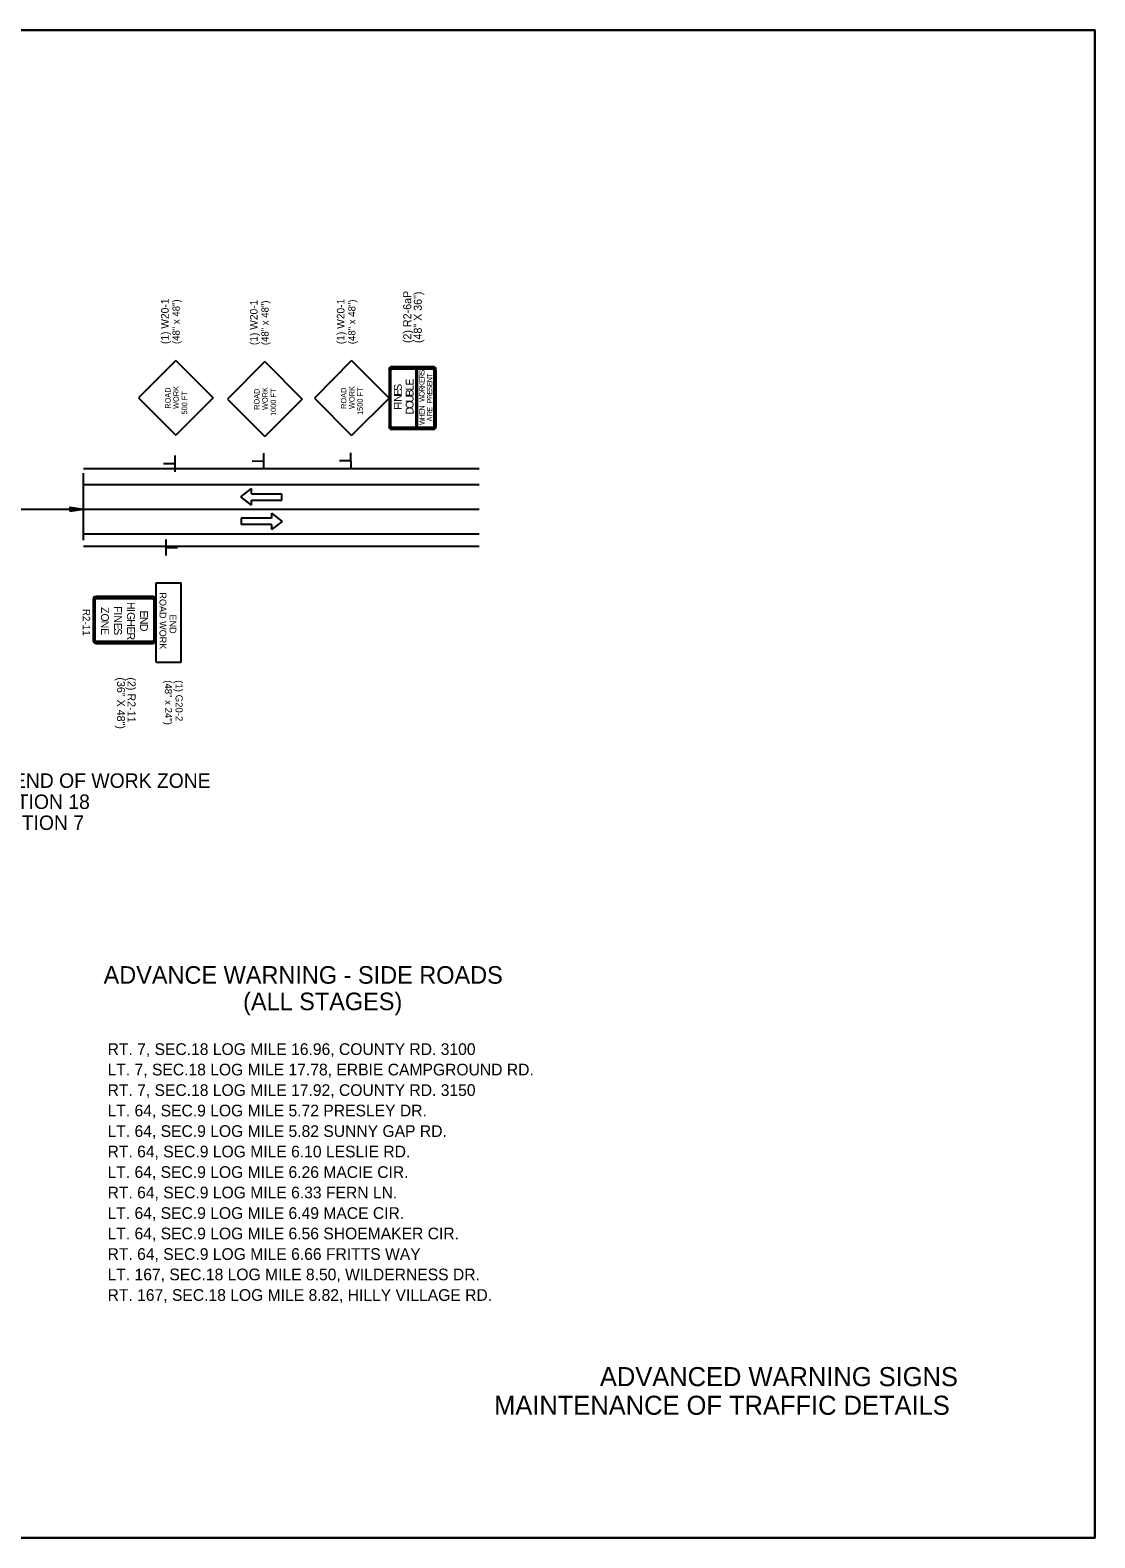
# Model space of a CAD drawing. Extents: x 32485 to 39285, y 55121 to 58033.
# Drawn here: x 38508 to 39285, y 56764 to 57864 of the extents above; entities that cross this region are included whole.
import ezdxf

# ---------------------------------------------------------------- set-up
doc = ezdxf.new("R2010")
doc.units = 0
for name, color, linetype in [('Default', 7, 'Continuous'), ('DSN_DRFT_Junk-No-Plot', 7, 'Continuous'), ('R_Border', 7, 'Continuous'), ('R_Draft', 7, 'Continuous'), ('R_Exist Surface', 7, 'Continuous'), ('R_MOT', 7, 'Continuous')]:
    doc.layers.add(name, color=color, linetype=linetype)

msp = doc.modelspace()

# ---------------------------------------------------------------- linework, layer by layer
at = {"layer": 'Default'}
for p, q in [((38802, 57618.3), (38772, 57618.3)), ((38769.9, 57616.2), (38769.9, 57574.8)), ((38770.5, 57616.2), (38770.5, 57574.8)), ((38771.3, 57574.8), (38771.3, 57616.2)), ((38802, 57617.8), (38772, 57617.8)), ((38772, 57616.9), (38802, 57616.9)), ((38789.7, 57574.1), (38789.7, 57616.9)), ((38789.7, 57616.9), (38790.5, 57616.9)), ((38790.5, 57616.9), (38790.5, 57574.1)), ((38802.7, 57616.2), (38802.7, 57574.8)), ((38803.6, 57574.8), (38803.6, 57616.2)), ((38804.2, 57574.8), (38804.2, 57616.2)), ((38802, 57574.1), (38772, 57574.1)), ((38790.5, 57574.1), (38789.7, 57574.1)), ((38772, 57573.3), (38802, 57573.3)), ((38772, 57572.7), (38802, 57572.7)), ((38546.9, 57491.7), (38546.9, 57540.7)), ((38661.8, 57523.4), (38669.6, 57529.4)), ((38669.6, 57517.4), (38661.8, 57523.4)), ((38669.6, 57525.6), (38669.6, 57529.4)), ((38669.6, 57525.6), (38691.7, 57525.6)), ((38669.6, 57521.1), (38691.7, 57521.1)), ((38669.6, 57517.4), (38669.6, 57521.1)), ((38691.7, 57521.1), (38691.7, 57525.6)), ((38289.1, 57514.5), (38546.9, 57514.5)), ((38684.1, 57511.5), (38684.1, 57507.8)), ((38684.1, 57511.5), (38691.9, 57505.5)), ((38684.1, 57507.8), (38662, 57507.8)), ((38662, 57507.8), (38662, 57503.3)), ((38684.1, 57503.3), (38662, 57503.3)), ((38691.9, 57505.5), (38684.1, 57499.5)), ((38684.1, 57503.3), (38684.1, 57499.5)), ((38554, 57448.6), (38554, 57418.6)), ((38554.6, 57448.6), (38554.6, 57418.6)), ((38555.4, 57418.6), (38555.4, 57448.6)), ((38597.5, 57450.7), (38556.1, 57450.7)), ((38597.5, 57450.1), (38556.1, 57450.1)), ((38556.1, 57449.3), (38597.5, 57449.3)), ((38598.2, 57448.6), (38598.2, 57418.6)), ((38599.1, 57418.6), (38599.1, 57448.6)), ((38599.7, 57418.6), (38599.7, 57448.6)), ((38597.5, 57417.9), (38556.1, 57417.9)), ((38556.1, 57417.1), (38597.5, 57417.1)), ((38556.1, 57416.5), (38597.5, 57416.5))]:
    msp.add_line(p, q, dxfattribs=at)
msp.add_lwpolyline([(37585, 57863.9), (37585, 56763.9), (39285, 56763.9), (39285, 57863.9)], close=True, dxfattribs=at)
for centre, radius, start, end in [((38772, 57616.2), 2.14, 90, 180), ((38802, 57616.2), 2.14, 0, 90), ((38772, 57616.2), 1.55, 90, 180), ((38772, 57616.2), 0.714, 90, 180), ((38802, 57616.2), 1.55, 0, 90), ((38802, 57616.2), 0.714, 0, 90), ((38772, 57574.8), 2.14, 180, 270), ((38772, 57574.8), 1.55, 180, 270), ((38772, 57574.8), 0.714, 180, 270), ((38802, 57574.8), 2.14, 270, 0), ((38802, 57574.8), 1.55, 270, 0), ((38802, 57574.8), 0.714, 270, 0), ((38556.1, 57448.6), 2.14, 90, 180), ((38556.1, 57448.6), 1.55, 90, 180), ((38556.1, 57448.6), 0.714, 90, 180), ((38597.5, 57448.6), 2.14, 0, 90), ((38597.5, 57448.6), 1.55, 0, 90), ((38597.5, 57448.6), 0.714, 0, 90), ((38556.1, 57418.6), 2.14, 180, 270), ((38556.1, 57418.6), 1.55, 180, 270), ((38556.1, 57418.6), 0.714, 180, 270), ((38597.5, 57418.6), 2.14, 270, 0), ((38597.5, 57418.6), 1.55, 270, 0), ((38597.5, 57418.6), 0.714, 270, 0)]:
    msp.add_arc(centre, radius, start, end, dxfattribs=at)
at = {"layer": 'DSN_DRFT_Junk-No-Plot'}
msp.add_lwpolyline([(37585, 57863.9), (39285, 57863.9), (39285, 56763.9), (37585, 56763.9)], close=True, dxfattribs=at)
at = {"layer": 'R_Border'}
for p, q in [((38614.4, 57622.9), (38587.1, 57595.6)), ((38614.4, 57622.9), (38641.6, 57595.6)), ((38679.3, 57622.1), (38652, 57594.8)), ((38679.3, 57622.1), (38706.5, 57594.8)), ((38742.6, 57622.8), (38715.4, 57595.5)), ((38742.6, 57622.8), (38769.9, 57595.5)), ((38587.1, 57595.6), (38614.4, 57568.3)), ((38641.6, 57595.6), (38614.4, 57568.3)), ((38652, 57594.8), (38679.3, 57567.5)), ((38706.5, 57594.8), (38679.3, 57567.5)), ((38715.4, 57595.5), (38742.6, 57568.2)), ((38769.9, 57595.5), (38742.6, 57568.2)), ((38613.5, 57553.5), (38613.7, 57541.7)), ((38678.2, 57555.3), (38678.4, 57543.6)), ((38741.8, 57555.6), (38742, 57543.8)), ((38613.4, 57547.6), (38605.4, 57547.5)), ((38678.1, 57549.5), (38670, 57549.3)), ((38741.7, 57549.8), (38733.7, 57549.6)), ((38607.3, 57480.6), (38607.3, 57492.4)), ((38607.5, 57486.4), (38615.5, 57486.5)), ((38599.9, 57402.8), (38599.9, 57460.7)), ((38599.9, 57460.7), (38618.1, 57460.7)), ((38618.1, 57402.8), (38618.1, 57460.7)), ((38599.9, 57402.8), (38618.1, 57402.8))]:
    msp.add_line(p, q, dxfattribs=at)
at = {"layer": 'R_Draft'}
for p, q in [((38536.9, 57516), (38546.9, 57514.5)), ((38536.9, 57516), (38536.9, 57513)), ((38536.9, 57515.8), (38545.2, 57514.5)), ((38536.9, 57515.5), (38543.5, 57514.5)), ((38536.9, 57515.3), (38541.8, 57514.5)), ((38536.9, 57515), (38540.1, 57514.5)), ((38536.9, 57514.7), (38538.5, 57514.5)), ((38536.9, 57513), (38546.9, 57514.5)), ((38536.9, 57514), (38540.1, 57514.5)), ((38536.9, 57513.5), (38543.5, 57514.5)), ((38536.9, 57513.3), (38545.2, 57514.5)), ((38536.9, 57513.8), (38541.8, 57514.5)), ((38536.9, 57514.3), (38538.5, 57514.5))]:
    msp.add_line(p, q, dxfattribs=at)
at = {"layer": 'R_Exist Surface'}
for p, q in [((38546.9, 57544), (38835.7, 57544)), ((38546.9, 57532.5), (38835.7, 57532.5)), ((38546.9, 57514.5), (38835.7, 57514.5)), ((38546.9, 57496.5), (38835.7, 57496.5)), ((38546.9, 57487.5), (38835.7, 57487.5))]:
    msp.add_line(p, q, dxfattribs=at)

# ---------------------------------------------------------------- texts
at = {"layer": 'Default'}
for s, height, rotation, p in [('E', 5.71, 90, (38787.8, 57604.6)), ('S', 3.81, 90, (38795.8, 57612.6)), ('R', 3.81, 90, (38795.8, 57609.6)), ('E', 3.81, 90, (38795.8, 57606.6)), ('T', 3.81, 90, (38801.5, 57610.2)), ('N', 3.81, 90, (38801.5, 57607)), ('E', 3.81, 90, (38801.5, 57604)), ('S', 5.71, 90, (38779.2, 57600.8)), ('E', 5.71, 90, (38779.2, 57597.2)), ('N', 5.71, 90, (38779.2, 57592.8)), ('L', 5.71, 90, (38787.8, 57600.9)), ('B', 5.71, 90, (38787.8, 57596.7)), ('U', 5.71, 90, (38787.8, 57592.2)), ('O', 3.81, 90, (38795.8, 57596.5)), ('K', 3.81, 90, (38795.8, 57603.3)), ('R', 3.81, 90, (38795.8, 57600.1)), ('W', 3.81, 90, (38795.8, 57592.7)), ('S', 3.81, 90, (38801.5, 57600.8)), ('E', 3.81, 90, (38801.5, 57598.1)), ('R', 3.81, 90, (38801.5, 57594.8)), ('I', 5.71, 90, (38779.2, 57590.7)), ('F', 5.71, 90, (38779.2, 57587)), ('O', 5.71, 90, (38787.8, 57587.7)), ('D', 5.71, 90, (38787.8, 57583.5)), ('N', 3.81, 90, (38795.8, 57586.3)), ('E', 3.81, 90, (38795.8, 57583.3)), ('P', 3.81, 90, (38801.5, 57591.7)), ('E', 3.81, 90, (38801.5, 57585.5)), ('R', 3.81, 90, (38801.5, 57582.3)), ('H', 3.81, 90, (38795.8, 57579.8)), ('W', 3.81, 90, (38795.8, 57575.8)), ('A', 3.81, 90, (38801.5, 57578.4)), ('Z', 5.71, 270, (38559.7, 57443)), ('F', 5.71, 270, (38569.2, 57443.6)), ('H', 5.71, 270, (38578.7, 57446.7)), ('R2-11', 5.38, 270, (38546.4, 57441.7)), ('O', 5.71, 270, (38559.7, 57438.3)), ('N', 5.71, 270, (38559.7, 57433)), ('I', 5.71, 270, (38569.2, 57439.2)), ('N', 5.71, 270, (38569.2, 57436.9)), ('G', 5.71, 270, (38578.7, 57439.3)), ('I', 5.71, 270, (38578.7, 57441.5)), ('H', 5.71, 270, (38578.7, 57434.1)), ('E', 5.71, 270, (38588.2, 57440.4)), ('N', 5.71, 270, (38588.2, 57435.9)), ('E', 5.71, 270, (38559.7, 57427.7)), ('S', 5.71, 270, (38569.2, 57427.5)), ('E', 5.71, 270, (38569.2, 57431.6)), ('E', 5.71, 270, (38578.7, 57428.9)), ('R', 5.71, 270, (38578.7, 57424.4)), ('D', 5.71, 270, (38588.2, 57430.7))]:
    msp.add_text(s, height=height, rotation=rotation, dxfattribs=at).set_placement(p)
for s, p in [('ADVANCE WARNING SIGNS AT BEGINNING AND END OF WORK ZONE', (38164.4, 57311.1)), ('HWY. 7, SECTION 18', (38412.7, 57295.7)), ('HWY. 65, SECTION 7', (38408.5, 57280.4))]:
    msp.add_text(s, height=10.557, dxfattribs=at).set_placement(p)
at = {"layer": 'R_Border'}
for s, height, rotation, p in [('(1) W20-1', 5.58, 90, (38609.1, 57634.9)), ('(48" x 48")', 5.233, 90, (38617.1, 57634.9)), ('(1) W20-1', 5.58, 90, (38674, 57634.1)), ('(48" x 48")', 5.233, 90, (38682, 57634.1)), ('(1) W20-1', 5.58, 90, (38737.4, 57634.8)), ('(48" x 48")', 5.233, 90, (38745.4, 57634.8)), ('ROAD', 4.02, 90.0004, (38610.5, 57587.7)), ('WORK', 4.02, 90, (38616.5, 57587.6)), (' 500 FT', 4.02, 90.0006, (38622.6, 57582)), ('ROAD', 4.02, 90.0004, (38675.4, 57586.9)), ('WORK', 4.02, 90, (38681.4, 57586.8)), ('1000 FT', 4.02, 90.0006, (38687.5, 57582.4)), ('ROAD', 4.02, 90.0004, (38738.8, 57587.6)), ('WORK', 4.02, 90, (38744.8, 57587.5)), ('1500 FT', 4.02, 90.0006, (38750.8, 57583.2)), ('ROAD WORK', 4.95, 270, (38602.4, 57453.7)), ('END', 4.95, 270, (38609.7, 57437.6)), ('(48" x 24")', 5.233, 270, (38606.3, 57389.6)), ('(1) G20-2', 5.23, 270, (38614.1, 57389.6))]:
    msp.add_text(s, height=height, rotation=rotation, dxfattribs=at).set_placement(p)
at = {"layer": 'R_Draft'}
for s, rotation, p in [('(2) R2-6aP', 90, (38786.1, 57635.6)), ('(48" X 36")', 90, (38793.8, 57635.6)), ('(36" X 48")', 270, (38571.4, 57391.7)), ('(2) R2-11', 270, (38579.1, 57391.7))]:
    msp.add_text(s, height=5.83, rotation=rotation, dxfattribs=at).set_placement(p)
for s, height, p in [('ADVANCE WARNING - SIDE ROADS', 12.813, (38561.6, 57168.2)), ('(ALL STAGES)', 12.813, (38663.4, 57148.9)), ('RT. 7, SEC.18 LOG MILE 16.96, COUNTY RD. 3100', 8.542, (38564.5, 57116.2)), ('LT. 7, SEC.18 LOG MILE 17.78, ERBIE CAMPGROUND RD.', 8.542, (38564.5, 57101.3)), ('RT. 7, SEC.18 LOG MILE 17.92, COUNTY RD. 3150', 8.542, (38564.5, 57086.3)), ('LT. 64, SEC.9 LOG MILE 5.72 PRESLEY DR.', 8.542, (38564.5, 57071.4)), ('LT. 64, SEC.9 LOG MILE 5.82 SUNNY GAP RD.', 8.542, (38564.5, 57056.4)), ('RT. 64, SEC.9 LOG MILE 6.10 LESLIE RD.', 8.542, (38564.5, 57041.5)), ('LT. 64, SEC.9 LOG MILE 6.26 MACIE CIR.', 8.542, (38564.5, 57026.5)), ('RT. 64, SEC.9 LOG MILE 6.33 FERN LN.', 8.542, (38564.5, 57011.6)), ('LT. 64, SEC.9 LOG MILE 6.49 MACE CIR.', 8.542, (38564.5, 56996.6)), ('LT. 64, SEC.9 LOG MILE 6.56 SHOEMAKER CIR.', 8.542, (38564.5, 56981.7)), ('RT. 64, SEC.9 LOG MILE 6.66 FRITTS WAY', 8.542, (38564.5, 56966.7)), ('LT. 167, SEC.18 LOG MILE 8.50, WILDERNESS DR. ', 8.542, (38564.5, 56951.8)), ('RT. 167, SEC.18 LOG MILE 8.82, HILLY VILLAGE RD. ', 8.542, (38564.5, 56936.8))]:
    msp.add_text(s, height=height, dxfattribs=at).set_placement(p)
at = {"layer": 'R_MOT'}
for s, p in [('ADVANCED WARNING SIGNS', (38923.8, 56874.6)), ('MAINTENANCE OF TRAFFIC DETAILS', (38846.6, 56853.7))]:
    msp.add_text(s, height=13.899, dxfattribs=at).set_placement(p)

doc.saveas('drawing.dxf')
